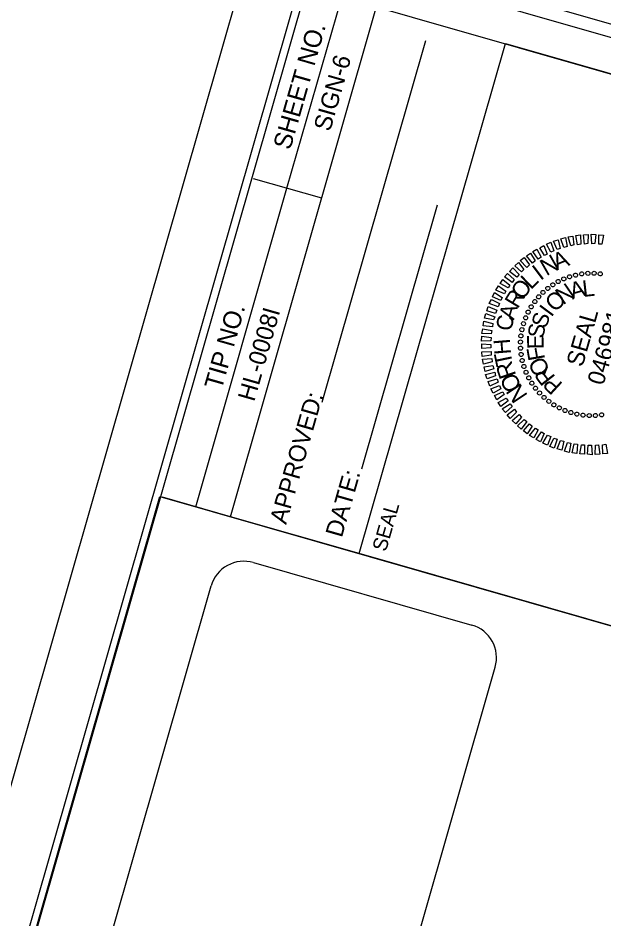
# Model space of a CAD drawing. Extents: x 2096093 to 2098911, y 683546 to 689764.
# Drawn here: x 2097369.3 to 2097575.6, y 689280.8 to 689598.1 of the extents above; entities that cross this region are included whole.
import ezdxf

# ---------------------------------------------------------------- set-up
doc = ezdxf.new("R2010")
doc.units = 0
for name, color, linetype in [('Default', 7, 'Continuous'), ('Old_Level_10', 7, 'Continuous'), ('Old_Level_2', 7, 'Continuous'), ('Old_Level_4', 7, 'Continuous'), ('Scratch_Level_5', 7, 'Continuous'), ('Sheet PE Seal Cell', 7, 'Continuous'), ('Sheet Plan CELL', 7, 'Continuous'), ('Sheet Plot Border Inside CELL', 7, 'Continuous'), ('Sheet Plot Border Outside CELL', 7, 'Continuous'), ('Sheet Title CELL', 7, 'Continuous')]:
    doc.layers.add(name, color=color, linetype=linetype)

msp = doc.modelspace()

# ---------------------------------------------------------------- linework, layer by layer
at = {"layer": 'Default'}
for p, q in [((2097463.95, 689538.15), (2097483.29, 689605.65)), ((2097463.95, 689538.15), (2097483.29, 689605.65)), ((2097444.05, 689422.43), (2097495.53, 689602.15)), ((2097444.05, 689422.43), (2097495.53, 689602.15)), ((2097476.32, 689462.78), (2097512.82, 689590.24)), ((2097476.32, 689462.78), (2097512.82, 689590.24)), ((2097476.19, 689534.64), (2097452.2, 689541.51)), ((2097476.19, 689534.64), (2097452.2, 689541.51)), ((2097476.19, 689534.64), (2097452.2, 689541.51)), ((2097476.19, 689534.64), (2097452.2, 689541.51)), ((2097431.81, 689425.93), (2097463.95, 689538.15)), ((2097431.81, 689425.93), (2097463.95, 689538.15)), ((2097490.31, 689439.34), (2097516.95, 689532.37)), ((2097490.31, 689439.34), (2097516.95, 689532.37)), ((2097444.05, 689422.43), (2097420.07, 689429.29)), ((2097444.05, 689422.43), (2097420.07, 689429.29))]:
    msp.add_line(p, q, dxfattribs=at)
at = {"layer": 'Old_Level_2'}
msp.add_line((2097489.39, 689409.44), (2097444.05, 689422.43), dxfattribs=at)
msp.add_line((2097489.39, 689409.44), (2097444.05, 689422.43), dxfattribs=at)
msp.add_lwpolyline([(2097489.39, 689409.44), (2097540.86, 689589.16), (2097647.94, 689558.5), (2097596.47, 689378.78)], close=True, dxfattribs=at)
msp.add_lwpolyline([(2097489.39, 689409.44), (2097540.86, 689589.16), (2097647.94, 689558.5), (2097596.47, 689378.78)], close=True, dxfattribs=at)
at = {"layer": 'Scratch_Level_5'}
msp.add_lwpolyline([(2098117.81, 688054.49), (2097347.73, 688084.03), (2097057.83, 688167.01), (2097419.22, 689429.54), (2097641.13, 689365.99), (2097692.54, 689545.54), (2098409.79, 689340.16), (2098316.63, 689014.71), (2098387.02, 688994.56)], close=True, dxfattribs=at)
at = {"layer": 'Sheet PE Seal Cell'}
for p, q in [((2097563.44, 689507), (2097563.44, 689507)), ((2097565.58, 689507.58), (2097565.58, 689507.58)), ((2097567.73, 689508.01), (2097567.73, 689508.01)), ((2097569.88, 689508.23), (2097569.88, 689508.23)), ((2097572.06, 689508.23), (2097572.06, 689508.23)), ((2097574.29, 689508.01), (2097574.29, 689508.01)), ((2097557.55, 689504.22), (2097557.55, 689504.22)), ((2097559.42, 689505.29), (2097559.42, 689505.29)), ((2097561.42, 689506.28), (2097561.42, 689506.28)), ((2097554.07, 689501.52), (2097554.07, 689501.52)), ((2097555.77, 689502.91), (2097555.77, 689502.91)), ((2097551.16, 689498.24), (2097551.16, 689498.24)), ((2097552.57, 689499.92), (2097552.57, 689499.92)), ((2097548.9, 689494.52), (2097548.9, 689494.52)), ((2097549.91, 689496.42), (2097549.91, 689496.42)), ((2097547.97, 689492.55), (2097547.97, 689492.55)), ((2097546.66, 689488.35), (2097546.66, 689488.35)), ((2097547.22, 689490.48), (2097547.22, 689490.48)), ((2097546.36, 689486.2), (2097546.36, 689486.2)), ((2097546.14, 689483.97), (2097546.14, 689483.97)), ((2097546.14, 689481.79), (2097546.14, 689481.79)), ((2097571.23, 689483.14), (2097571.23, 689483.14)), ((2097546.35, 689479.65), (2097546.35, 689479.65)), ((2097546.78, 689477.5), (2097546.78, 689477.5)), ((2097547.36, 689475.35), (2097547.36, 689475.35)), ((2097548.08, 689473.33), (2097548.08, 689473.33)), ((2097549.07, 689471.33), (2097549.07, 689471.33)), ((2097550.15, 689469.46), (2097550.15, 689469.46)), ((2097551.46, 689467.68), (2097551.46, 689467.68)), ((2097552.84, 689465.98), (2097552.84, 689465.98)), ((2097554.44, 689464.49), (2097554.44, 689464.49)), ((2097556.12, 689463.07), (2097556.12, 689463.07)), ((2097557.95, 689461.82), (2097557.95, 689461.82)), ((2097559.84, 689460.81), (2097559.84, 689460.81)), ((2097561.81, 689459.88), (2097561.81, 689459.88)), ((2097563.88, 689459.13), (2097563.88, 689459.13)), ((2097566.01, 689458.57), (2097566.01, 689458.57)), ((2097568.16, 689458.27), (2097568.16, 689458.27)), ((2097570.39, 689458.05), (2097570.39, 689458.05)), ((2097572.57, 689458.05), (2097572.57, 689458.05)), ((2097574.72, 689458.27), (2097574.72, 689458.27))]:
    msp.add_line(p, q, dxfattribs=at)
for points in [[(2097559.11, 689516.56), (2097557.76, 689519.5), (2097559.42, 689520.01), (2097560.18, 689516.88)], [(2097561.43, 689517.25), (2097560.34, 689520.32), (2097562.04, 689520.82), (2097562.59, 689517.65)], [(2097563.91, 689517.89), (2097563, 689521.07), (2097564.66, 689521.27), (2097564.99, 689518.21)], [(2097566.25, 689518.26), (2097565.62, 689521.51), (2097567.34, 689521.7), (2097567.44, 689518.44)], [(2097568.76, 689518.48), (2097568.35, 689521.77), (2097569.99, 689521.87), (2097569.9, 689518.67)], [(2097571.28, 689518.59), (2097571.06, 689521.98), (2097572.73, 689521.82), (2097572.39, 689518.64)], [(2097573.76, 689518.51), (2097573.71, 689521.8), (2097575.43, 689521.62), (2097574.85, 689518.51)], [(2097552.43, 689513.22), (2097550.49, 689515.91), (2097551.98, 689516.73), (2097553.41, 689513.93)], [(2097554.61, 689514.47), (2097552.94, 689517.19), (2097554.42, 689518.01), (2097555.58, 689514.97)], [(2097556.82, 689515.66), (2097555.29, 689518.49), (2097556.88, 689519.13), (2097557.97, 689516.06)], [(2097548.41, 689510.26), (2097546.1, 689512.75), (2097547.47, 689513.71), (2097549.29, 689511.16)], [(2097550.42, 689511.82), (2097548.28, 689514.36), (2097549.7, 689515.31), (2097551.35, 689512.54)], [(2097544.84, 689506.87), (2097542.34, 689508.88), (2097543.44, 689510.18), (2097545.67, 689507.77)], [(2097546.57, 689508.76), (2097544.21, 689510.84), (2097545.44, 689512.05), (2097547.41, 689509.51)], [(2097543.3, 689504.97), (2097540.59, 689506.94), (2097541.55, 689508.12), (2097543.96, 689505.97)], [(2097540.53, 689500.92), (2097537.55, 689502.3), (2097538.4, 689503.82), (2097541.06, 689501.86)], [(2097541.82, 689503.05), (2097539.05, 689504.62), (2097539.95, 689505.98), (2097542.44, 689503.96)], [(2097539.3, 689498.62), (2097536.35, 689499.93), (2097537.05, 689501.45), (2097539.78, 689499.73)], [(2097538.26, 689496.42), (2097535.19, 689497.51), (2097535.93, 689499.01), (2097538.78, 689497.52)], [(2097536.72, 689491.77), (2097533.52, 689492.42), (2097534.03, 689493.99), (2097537.1, 689492.91)], [(2097537.43, 689494.06), (2097534.3, 689494.96), (2097534.8, 689496.53), (2097537.8, 689495.2)], [(2097536.27, 689489.3), (2097533.04, 689489.65), (2097533.32, 689491.34), (2097536.46, 689490.49)], [(2097535.9, 689486.91), (2097532.6, 689487.02), (2097532.91, 689488.65), (2097536.08, 689488.1)], [(2097535.77, 689484.45), (2097532.45, 689484.3), (2097532.58, 689486.04), (2097535.81, 689485.53)], [(2097535.73, 689481.96), (2097532.53, 689481.68), (2097532.52, 689483.3), (2097535.68, 689483.07)], [(2097535.83, 689479.39), (2097532.68, 689478.93), (2097532.52, 689480.54), (2097535.88, 689480.67)], [(2097536.23, 689476.98), (2097533.1, 689476.21), (2097532.85, 689477.9), (2097536.1, 689478.16)], [(2097536.79, 689474.58), (2097533.69, 689473.55), (2097533.34, 689475.26), (2097536.48, 689475.66)], [(2097537.39, 689472.13), (2097534.43, 689471.05), (2097533.87, 689472.56), (2097537.11, 689473.35)], [(2097538.31, 689469.89), (2097535.41, 689468.48), (2097534.77, 689470.07), (2097537.94, 689470.98)], [(2097539.25, 689467.54), (2097536.53, 689466.03), (2097535.7, 689467.51), (2097538.84, 689468.64)], [(2097540.47, 689465.47), (2097537.8, 689463.58), (2097537.04, 689465.1), (2097539.93, 689466.46)], [(2097541.82, 689463.26), (2097539.23, 689461.3), (2097538.28, 689462.72), (2097541.15, 689464.18)], [(2097543.23, 689461.3), (2097540.86, 689459.17), (2097539.72, 689460.48), (2097542.5, 689462.18)], [(2097544.74, 689459.31), (2097542.53, 689457.03), (2097541.46, 689458.37), (2097544.1, 689460.32)], [(2097546.48, 689457.56), (2097544.49, 689455.16), (2097543.21, 689456.31), (2097545.73, 689458.4)], [(2097548.42, 689455.97), (2097546.46, 689453.3), (2097545.17, 689454.45), (2097547.5, 689456.75)], [(2097550.26, 689454.4), (2097548.54, 689451.67), (2097547.23, 689452.72), (2097549.4, 689455.22)], [(2097552.36, 689453.02), (2097550.88, 689450.22), (2097549.39, 689451.01), (2097551.46, 689453.69)], [(2097554.49, 689451.73), (2097553.25, 689448.86), (2097551.71, 689449.67), (2097553.59, 689452.41)], [(2097556.83, 689450.65), (2097555.66, 689447.65), (2097554.08, 689448.31), (2097555.74, 689451.22)], [(2097559.07, 689449.75), (2097558.08, 689446.65), (2097556.52, 689447.2), (2097557.94, 689450.17)], [(2097561.46, 689449.01), (2097560.71, 689445.84), (2097559.07, 689446.31), (2097560.3, 689449.34)], [(2097563.87, 689448.37), (2097563.36, 689445.13), (2097561.7, 689445.51), (2097562.69, 689448.6)], [(2097566.26, 689448), (2097566.04, 689444.68), (2097564.37, 689445), (2097565.05, 689448.14)], [(2097568.69, 689447.77), (2097568.74, 689444.48), (2097567.02, 689444.66), (2097567.6, 689447.77)], [(2097571.17, 689447.69), (2097571.39, 689444.29), (2097569.72, 689444.46), (2097570.06, 689447.64)], [(2097573.69, 689447.79), (2097574.1, 689444.5), (2097572.46, 689444.4), (2097572.55, 689447.6)], [(2097576.2, 689448.01), (2097576.83, 689444.76), (2097575.11, 689444.58), (2097575.01, 689447.83)]]:
    msp.add_lwpolyline(points, close=True, dxfattribs=at)
for centre, major_axis in [((2097561.42, 689506.22), (-0.282, 0.663)), ((2097563.46, 689506.99), (-0.223, 0.685)), ((2097565.57, 689507.57), (-0.162, 0.701)), ((2097567.72, 689507.97), (-0.101, 0.713)), ((2097569.9, 689508.18), (-0.038, 0.719)), ((2097572.09, 689508.2), (0.025, 0.72)), ((2097574.27, 689508.03), (0.087, 0.715)), ((2097555.78, 689502.89), (-0.444, 0.567)), ((2097557.56, 689504.17), (-0.392, 0.604)), ((2097559.44, 689505.28), (-0.338, 0.636)), ((2097552.58, 689499.91), (-0.535, 0.482)), ((2097554.11, 689501.47), (-0.491, 0.526)), ((2097549.95, 689496.42), (-0.611, 0.381)), ((2097551.19, 689498.22), (-0.575, 0.433)), ((2097548.87, 689494.51), (-0.642, 0.327)), ((2097547.24, 689490.46), (-0.689, 0.21)), ((2097547.97, 689492.52), (-0.668, 0.269)), ((2097546.69, 689488.34), (-0.704, 0.149)), ((2097546.16, 689484), (-0.72, 0.025)), ((2097546.33, 689486.18), (-0.715, 0.087)), ((2097546.18, 689481.81), (-0.719, -0.038)), ((2097546.39, 689479.64), (-0.713, -0.101)), ((2097546.79, 689477.49), (-0.701, -0.162)), ((2097547.38, 689475.38), (-0.685, -0.223)), ((2097548.14, 689473.33), (-0.663, -0.282)), ((2097549.09, 689471.35), (-0.636, -0.338)), ((2097550.2, 689469.47), (-0.604, -0.392)), ((2097551.47, 689467.69), (-0.567, -0.444)), ((2097552.89, 689466.03), (-0.526, -0.491)), ((2097554.45, 689464.49), (-0.482, -0.535)), ((2097556.14, 689463.1), (-0.433, -0.575)), ((2097557.94, 689461.86), (-0.381, -0.611)), ((2097559.85, 689460.79), (-0.327, -0.642)), ((2097561.84, 689459.88), (-0.269, -0.668)), ((2097563.9, 689459.15), (-0.21, -0.689)), ((2097566.02, 689458.6), (-0.149, -0.704)), ((2097568.18, 689458.24), (-0.087, -0.715)), ((2097574.73, 689458.3), (0.101, -0.713)), ((2097570.36, 689458.07), (-0.025, -0.72)), ((2097572.55, 689458.09), (0.038, -0.719))]:
    msp.add_ellipse(centre, major_axis=major_axis, ratio=0.999708, dxfattribs=at)
at = {"layer": 'Sheet Plan CELL'}
msp.add_lwpolyline([(2097470.8, 689609.08), (2097057.86, 688167.12), (2098067.29, 687878.05), (2098480.22, 689319.99)], close=True, dxfattribs=at)
at = {"layer": 'Sheet Plot Border Inside CELL'}
msp.add_lwpolyline([(2098027.26, 687729.7), (2098485.9, 689331.31), (2097471.68, 689621.77), (2097013.02, 688020.15)], close=True, dxfattribs=at)
msp.add_lwpolyline([(2098027.26, 687729.7), (2098485.9, 689331.31), (2097471.68, 689621.77), (2097013.02, 688020.15)], close=True, dxfattribs=at)
at = {"layer": 'Sheet Plot Border Outside CELL'}
msp.add_lwpolyline([(2098042.9, 687711.7), (2098506.38, 689330.14), (2097453.69, 689631.6), (2096990.22, 688013.15)], close=True, dxfattribs=at)
msp.add_lwpolyline([(2098042.9, 687711.7), (2098506.38, 689330.14), (2097453.69, 689631.6), (2096990.22, 688013.15)], close=True, dxfattribs=at)
at = {"layer": 'Sheet Title CELL'}
for p, q in [((2097452.11, 689406.31), (2097529.03, 689384.29)), ((2097400.17, 689268.49), (2097437.27, 689398.08)), ((2097418.03, 688952.89), (2097537.27, 689369.45))]:
    msp.add_line(p, q, dxfattribs=at)
for centre, start, end in [((2097448.8, 689394.77), 74.0259, 164.0259), ((2097525.73, 689372.75), 344.0259, 74.0259)]:
    msp.add_arc(centre, 12, start, end, dxfattribs=at)

# ---------------------------------------------------------------- texts
at = {"layer": 'Default'}
for s, height, p in [('SHEET NO.', 6.356, (2097465.09, 689551.37)), ('SHEET NO.', 6.356, (2097465.09, 689551.37)), ('SIGN-6', 6.108, (2097479.12, 689557.86)), ('TIP NO.', 6.356, (2097440.89, 689466.87)), ('TIP NO.', 6.356, (2097440.89, 689466.87)), ('HL-0008I', 6.108, (2097452.41, 689462.73))]:
    msp.add_text(s, height=height, rotation=74.0148, dxfattribs=at).set_placement(p)
at = {"layer": 'Old_Level_10'}
msp.add_text('SEAL', height=5.093, rotation=74.0148, dxfattribs=at).set_placement((2097498.79, 689409.9))
msp.add_text('SEAL', height=5.093, rotation=74.0148, dxfattribs=at).set_placement((2097498.79, 689409.9))
at = {"layer": 'Old_Level_4'}
for s, p in [('APPROVED:', (2097463.65, 689419.5)), ('APPROVED:', (2097463.65, 689419.5)), ('DATE:', (2097483.26, 689414.84)), ('DATE:', (2097483.26, 689414.84))]:
    msp.add_text(s, height=6.108, rotation=74.0148, dxfattribs=at).set_placement(p)
at = {"layer": 'Sheet PE Seal Cell'}
for s, height, rotation, p in [('N', 5.98, 29.8448, (2097555.3, 689507.1)), ('A', 5.95, 22.643, (2097558.95, 689509.12)), ('I', 5.97, 37.046, (2097553.22, 689505.45)), ('L', 5.93, 44.2468, (2097549.8, 689502.22)), ('O', 5.85, 51.4471, (2097546.81, 689498.5)), ('N', 5.98, 34.5025, (2097561.12, 689496.9)), ('A', 5.89, 15.7862, (2097564.41, 689498.92)), ('L', 5.79, 6.4267, (2097568.26, 689499.85)), ('R', 5.75, 58.647, (2097545.17, 689495.49)), ('O', 5.93, 43.8594, (2097558.28, 689494.23)), ('I', 5.82, 53.2155, (2097557.05, 689492.5)), ('A', 5.64, 73.0462, (2097543.82, 689491.5)), ('S', 5.64, 71.9263, (2097555.2, 689488.56)), ('SEAL', 5.998, 74.0259, (2097567.99, 689474.91)), ('046981', 5.998, 74.0259, (2097575.35, 689468.46)), ('C', 5.66, 80.2458, (2097543.02, 689487.62)), ('S', 5.67, 81.2815, (2097554.26, 689485.08)), ('H', 5.82, 94.6454, (2097542.85, 689479.77)), ('E', 5.77, 90.637, (2097554.32, 689481.48)), ('F', 5.89, 99.9929, (2097554.88, 689477.99)), ('T', 5.91, 101.8457, (2097543.54, 689476.19)), ('O', 5.98, 118.7071, (2097556.8, 689474)), ('R', 5.97, 109.0464, (2097544.72, 689472.31)), ('R', 5.93, 128.0655, (2097558.68, 689471.65)), ('O', 5.98, 116.2476, (2097546.75, 689468.14)), ('N', 5.96, 123.4494, (2097548.91, 689465.13)), ('P', 5.83, 137.4248, (2097561.31, 689469.23))]:
    msp.add_text(s, height=height, rotation=rotation, dxfattribs=at).set_placement(p)

doc.saveas('drawing.dxf')
